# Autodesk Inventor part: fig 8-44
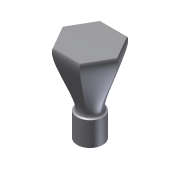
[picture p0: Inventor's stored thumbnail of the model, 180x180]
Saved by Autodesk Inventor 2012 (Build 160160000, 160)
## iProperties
Created: 2004-05
Part Number: fig 8-44
Document SubType Name: Modeling
Designer: CADCIM Technologies
Manufacturer: Standard
Standards Organization: Custom
Density: 1 g/cm^3
Material: Default
Author: CADCIM Technologies
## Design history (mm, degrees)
sketch "Sketch1"
  geometry: C1 r 16.344 at (0, 0)
  constraints: 1 centre point
extrude "Extrusion1" new body sketch "Sketch1" distance "d0" = 30.75; taper "d1" = 0 deg
workplane "Work Plane1"
sketch "Sketch2"
  geometry: L1 (34.788, 0)-(17.394, -30.128); L2 (17.394, -30.128)-(-17.394, -30.128); L3 (-17.394, -30.128)-(-34.788, 0); L4 (-34.788, 0)-(-17.394, 30.128); L5 (-17.394, 30.128)-(17.394, 30.128); L6 (17.394, 30.128)-(34.788, 0); 2 further points
  constraints: 12 end point, 1 coincident, 12 other
loft "Loft2" sketch "Sketch2" dims "d9" = 5, "d10" = 90 deg, "d11" = 40, "d12" = 120 deg
  node "Edges2"
body "Solid1"
other parameters: "d2" = 75
